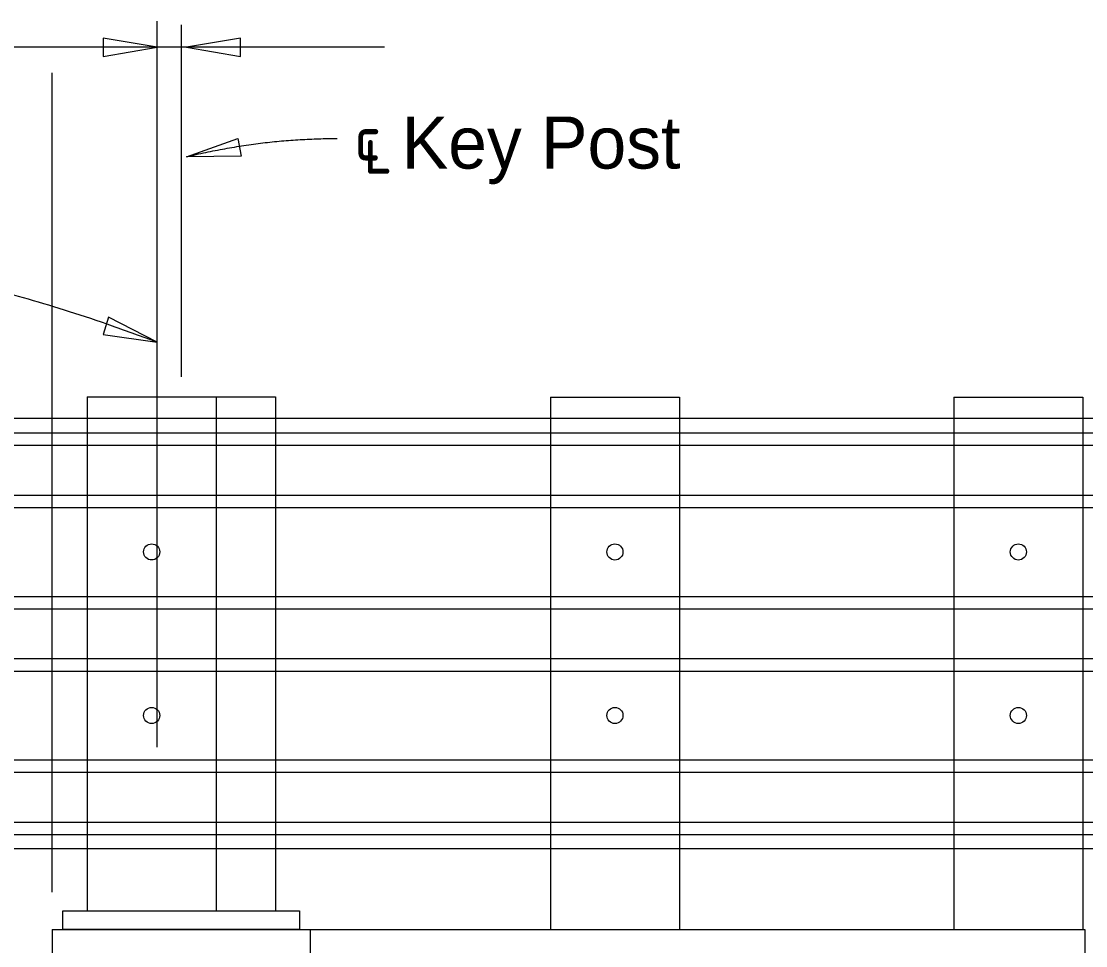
# Model space of a CAD drawing. Extents: x 21526.6 to 21598.7, y 56118.1 to 56155.9.
# Drawn here: x 21535.613 to 21539.735, y 56135.148 to 56138.727 of the extents above; entities that cross this region are included whole.
import ezdxf

# ---------------------------------------------------------------- set-up
doc = ezdxf.new("R2010")
doc.units = 0
for name, color, linetype in [('AdhocPoint_dp', 7, 'Continuous'), ('Border', 7, 'Continuous'), ('Patterning', 7, 'Continuous'), ('PlotBorder_dp', 7, 'Continuous'), ('SheetBorder_dp', 7, 'Continuous'), ('SubStrConc', 7, 'Continuous')]:
    doc.layers.add(name, color=color, linetype=linetype)

msp = doc.modelspace()

# ---------------------------------------------------------------- linework, layer by layer
at = {"layer": 'AdhocPoint_dp'}
for q in [(21535.7321, 56132.6054), (21536.7321, 56135.2101)]:
    msp.add_line((21535.7321, 56135.2101), q, dxfattribs=at)
at = {"layer": 'Patterning'}
for p, q in [((21536.1385, 56135.9162), (21536.1385, 56138.7274)), ((21536.2322, 56138.7132), (21536.2322, 56137.3509)), ((21535.8675, 56137.2726), (21536.5967, 56137.2726)), ((21535.8675, 56137.2726), (21535.8675, 56135.283)), ((21536.3675, 56137.2726), (21536.3675, 56135.283)), ((21537.6617, 56137.2725), (21537.6617, 56135.21)), ((21537.6617, 56137.2725), (21538.1617, 56137.2725)), ((21538.1617, 56137.2725), (21538.1617, 56135.21)), ((21539.2242, 56137.2725), (21539.2242, 56135.21)), ((21539.2242, 56137.2725), (21539.7242, 56137.2725)), ((21539.7242, 56137.2725), (21539.7242, 56135.21))]:
    msp.add_line(p, q, dxfattribs=at)
for centre in [(21536.1175, 56136.6725), (21536.1175, 56136.0393)]:
    msp.add_circle(centre, 0.0312, dxfattribs=at)
at = {"layer": 'PlotBorder_dp'}
for p, q in [((21537.0187, 56138.6267), (21533.9069, 56138.6267)), ((21535.7322, 56135.3555), (21535.7322, 56138.5276))]:
    msp.add_line(p, q, dxfattribs=at)
for points in [[(21536.1385, 56138.6267), (21535.9302, 56138.662), (21535.9302, 56138.5914)], [(21536.253, 56138.6267), (21536.4613, 56138.5914), (21536.4613, 56138.662)], [(21536.253, 56138.2023), (21536.4517, 56138.2741), (21536.4642, 56138.2047)], [(21536.1385, 56137.4853), (21535.9508, 56137.5821), (21535.9294, 56137.5149)]]:
    msp.add_lwpolyline(points, close=True, dxfattribs=at)
for points in [[(21536.253, 56138.2028), (21536.5445, 56138.2736), (21536.8361, 56138.2736)], [(21534.0219, 56137.7575), (21534.2745, 56137.7636), (21535.2881, 56137.8053), (21536.1385, 56137.4852)]]:
    msp.add_open_spline(points, degree=2, dxfattribs=at)
at = {"layer": 'SheetBorder_dp'}
for p, q in [((21536.0134, 56137.2726), (21536.0967, 56137.2726)), ((21536.5967, 56137.2726), (21536.5967, 56135.283)), ((21541.6829, 56137.1892), (21534.1592, 56137.1892)), ((21534.1592, 56137.1336), (21541.6829, 56137.1336)), ((21534.1592, 56137.0854), (21541.6829, 56137.0854)), ((21534.1592, 56136.8926), (21541.6829, 56136.8926)), ((21534.1592, 56136.8444), (21541.6829, 56136.8444)), ((21534.1592, 56136.5004), (21541.6829, 56136.5004)), ((21534.1592, 56136.4522), (21541.6829, 56136.4522)), ((21534.1592, 56136.2594), (21541.6829, 56136.2594)), ((21534.1592, 56136.2112), (21541.6829, 56136.2112)), ((21534.1592, 56135.8673), (21541.6829, 56135.8673)), ((21534.1592, 56135.8191), (21541.6829, 56135.8191)), ((21534.1592, 56135.6262), (21541.6829, 56135.6262)), ((21534.1592, 56135.578), (21541.6829, 56135.578)), ((21541.6829, 56135.5225), (21534.1592, 56135.5225))]:
    msp.add_line(p, q, dxfattribs=at)
msp.add_lwpolyline([(21535.7738, 56135.2101), (21535.7738, 56135.283), (21536.6905, 56135.283), (21536.6905, 56135.2101)], close=True, dxfattribs=at)
for centre in [(21537.9117, 56136.6724), (21539.4742, 56136.6724), (21537.9117, 56136.0393), (21539.4742, 56136.0393)]:
    msp.add_circle(centre, 0.0312, dxfattribs=at)
at = {"layer": 'SubStrConc'}
for p, q in [((21536.7321, 56134.46), (21536.7321, 56135.2101)), ((21536.7321, 56135.2101), (21539.7321, 56135.2101)), ((21539.7321, 56135.2101), (21539.7321, 56134.46))]:
    msp.add_line(p, q, dxfattribs=at)

# ---------------------------------------------------------------- texts
at = {"layer": 'Border'}
msp.add_text('℄ Key Post', height=0.2016, dxfattribs=at).set_placement((21536.902, 56138.1571))

doc.saveas('drawing.dxf')
